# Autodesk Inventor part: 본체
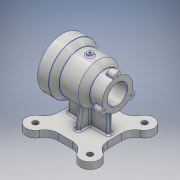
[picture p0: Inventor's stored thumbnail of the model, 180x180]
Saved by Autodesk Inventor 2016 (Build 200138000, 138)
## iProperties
Created: 2017-03
Part Number: 본체
Material: 알루미늄 6061
Document SubType Name: Modeling
Designer: USER
Density: 2.7 g/cm^3
Appearance: 알루미늄 - 평지
Mass: 1015.99 g
Surface Area: 852.536 cm^2
Volume: 376.292 cm^3
Author: USER
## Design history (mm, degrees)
sketch "스케치1"
  geometry: L1 (0, 0)-(-100, 0); L2 (0, 35)-(0, 45); L3 (0, 45)-(-20, 45); L4 (-20, 45)-(-31, 36.63); L5 (-31, 36.63)-(-65, 36.63); L6 (-65, 36.63)-(-77, 27.5); L7 (-77, 27.5)-(-100, 27.5); L8 (0, 35)-(-20, 35); L9 (-23, 32)-(-23, 29); L10 (-26, 26)-(-67, 26); L11 (-70, 23)-(-70, 20.5); L12 (-73, 17.5)-(-100, 17.5); L13 (-100, 17.5)-(-100, 27.5); A1 r 3 centre (-20, 32) between (-20, 35) and (-23, 32); A2 r 3 centre (-67, 23) between (-67, 26) and (-70, 23); A3 r 3 centre (-26, 29) between (-26, 26) and (-23, 29); A4 r 3 centre (-73, 20.5) between (-73, 17.5) and (-70, 20.5); 5 further points
  constraints: 26 end point, 8 point on circle, 8 point on line, 8 tangent, 6 perpendicular, 4 centre point, 3 parallel, 2 equal radius, 1 horizontal, 1 midpoint, 1 vertical, 1 vertical alignment
  dimensions: "d0" = 100 distance between parallel lines of L13 L2; "d1" = 90 diameter of L3 L1; "d2" = 70 diameter of L8 L1; "d3" = 52 diameter of L10 L1; "d4" = 23 distance between parallel lines of L9 L2; "d5" = 47 distance between parallel lines of L11 L9; "d6" = 35 diameter of L12 L1; "d7" = 20 distance of L2.end L3.end; "d8" = 31 horizontal distance of L4.end L2.end; "d9" = 65 horizontal distance of L2.end L5.end; "d10" = 23 distance of L6.end L7.end; "d11" = 55 diameter of L7 L1; "d20" = 3 radius of A1; "d24" = 3 radius of A4
revolve "회전1" sketch "스케치1" stored, may be unused: angle "d12" = 90 deg
sketch "스케치2"
  geometry: L1 (0, 0)-(13.75, 23.816); L2 (0, 0)-(-27.5, 0); L3 (0, 0)-(13.75, -23.816); A1 r 7 centre (-27.5, 0) between (-26.609, 6.943) and (-26.609, -6.943); A2 r 7 centre (13.75, -23.816) between (7.292, -26.516) and (19.317, -19.573); A3 r 7 centre (13.75, 23.816) between (19.317, 19.573) and (7.292, 26.516); 2 further points
  constraints: 6 end point, 6 point on circle, 3 centre point, 1 horizontal, 1 horizontal alignment, 10 other
  dimensions: "d13" = 120 deg angle of L1 L2; "d14" = 120 deg angle of L2 L3; "d15" = 14 diameter of A1; "d16" = 14 diameter of A3; "d17" = 14 diameter of A2
extrude "돌출1" join sketch "스케치2" distance "d18" = 15; taper "d19" = 0 deg
fillet "모깎기1" dims "d21" = 3
fillet "모깎기2" dims "d22" = 1
fillet "모깎기3" dims "d23" = 1
node "작업 평면1"
sketch "스케치8"
  geometry: L1 (50, 0)-(99.497, 49.497); L2 (50, 0)-(120, 0); L3 (5, 45)-(95, 45); L4 (95, 45)-(95, -45); L5 (95, -45)-(5, -45); L6 (5, -45)-(5, 45); L7 (5, 0)-(95, 0); L8 (50, -45)-(50, 45); A1 r 70 centre (50, 0) between (99.497, 49.497) and (120, 0); 1 further point
  constraints: 16 end point, 5 midpoint, 2 horizontal, 2 horizontal alignment, 2 parallel, 2 point on circle, 1 centre point, 1 perpendicular
  dimensions: "d82" = 140 diameter of A1; "d83" = 50 distance of L1.start point (0, 0); "d84" = 45 deg angle of L2 L1; "d88" = 90 distance of L3.start L3.end; "d89" = 90 distance of L5.end L3.start
extrude "돌출3" join sketch "스케치8" distance "d90" = 12; taper "d91" = 0 deg
sketch "스케치9"
  geometry: L1 (5, -45)-(5, 45) reference; L2 (5, 0)-(95, 0); L3 (95, 45)-(95, -45) reference; L4 (95, -45)-(5, -45) reference; L5 (5, 45)-(95, 45) reference; L6 (50, 45)-(50, -45); L7 (50, 0)-(99.497, 49.497); A1 r 70 centre (50, 0) between (99.497, 49.497) and (110.143, 35.816); A2 r 17 centre (99.497, 49.497) between (107.796, 34.661) and (84.661, 57.796); A3 r 25 centre (120, 12.842) between (110.143, 35.816) and (95, 12.842); A4 r 25 centre (62.842, 70) between (62.842, 45) and (85.816, 60.143); 1 further point
  constraints: 11 point on circle, 6 end point, 5 midpoint, 4 centre point, 4 tangent, 2 point on line, 1 coincident
  dimensions: "d92" = 140 diameter of A1; "d93" = 45 deg angle of L2 L7; "d94" = 34 diameter of A2; "d97" = 50 diameter of A3; "d98" = 50 diameter of A4
extrude "돌출4" join sketch "스케치9" distance "d99" = 12; taper "d100" = 0 deg
sketch "스케치11"
  geometry: C1 r 5 at (50, 0); 1 further point
  constraints: 1 centre point, 1 horizontal alignment
  dimensions: "d112" = 10 diameter of C1; "d113" = 50 distance of C1.centre point (0, 0)
extrude "돌출5" cut sketch "스케치11" distance "d114" = 12; taper "d115" = 0 deg
sketch "스케치12"
  geometry: C1 r 5 at (50, 0); C2 r 5 at (50, 0) reference; 1 further point
  constraints: 1 centre point, 1 concentric
  dimensions: "d119" = 10 diameter of C1
extrude "돌출6" join sketch "스케치12" distance "d120" = 12; taper "d121" = 0 deg
sketch "스케치13"
  geometry: L1 (16.497, -70)-(16.497, -82) reference; L2 (-116.497, -70)-(-116.497, -82) reference; L3 (-13, -45)-(-13, -70); L4 (-87, -27.5)-(-87, -70); L5 (-84.661, -70)-(-62.842, -70) reference; L6 (-76.732, -27.704)-(-65, -36.63) reference; L7 (-37.158, -82)-(-62.842, -82) reference; L8 (-50, 46.891)-(-50, -110.432); L9 (-19.663, -45)-(0, -45) reference; L10 (-100, -19.881)-(-88, -19.881) reference; L11 (-100, -19.881)-(-100, -19.881) reference; L12 (-88, -19.881)-(-100, -19.881) reference; L13 (-84, -10.332)-(-84, -16.905) reference; L14 (-100, -6.513)-(-88, -6.513) reference; L15 (-100, -6.513)-(-100, 26.395) reference; L16 (-88, 26.395)-(-100, 26.395) reference; L17 (-84, 27.237)-(-84, 27.237) reference; L18 (-100, 26.395)-(-88, 26.395) reference; L19 (-100, 26.395)-(-100, -6.513) reference; L20 (-88, -6.513)-(-100, -6.513) reference; L21 (-84, -16.905)-(-84, -10.332) reference; L22 (-77.337, -27.5)-(-77.337, 27.5) reference; L23 (-100, -27.5)-(-77.337, -27.5) reference; L24 (-13, -70)-(-87, -70); L25 (16.497, -70)-(-15.339, -70) reference; L26 (-20.268, -44.796)-(-20.268, 44.796) reference; L27 (-13, -45)-(-20.268, -44.796); L28 (-30.732, 36.835)-(-30.732, -36.835) reference; L29 (-20.268, -44.796)-(-30.732, -36.835); L30 (-30.732, -36.835)-(-20.268, -44.796) reference; L31 (-30.732, -36.835)-(-77.337, -27.5); 2 further points
  constraints: 14 end point, 3 point on line, 3 vertical, 2 collinear, 6 other
  dimensions: "d122" = 50 distance from line of point (0, 0) L8; "d123" = 37 distance between parallel lines of L3 L8; "d124" = 37 distance between parallel lines of L4 L8
extrude "돌출7" join sketch "스케치13" stored distance "d125" = 8; taper "d126" = 0 deg
node "작업 평면2"
sketch "스케치14"
  geometry: L1 (-25, -70)-(-19.784, -40.418); L2 (25, -70)-(19.784, -40.418); L3 (0, 0)-(0, -82); L4 (-12.842, -82)-(12.842, -82) reference; L5 (-34.661, -70)-(-66.497, -70) reference; L6 (-34.661, -70)-(-12.842, -70) reference; L7 (12.842, -70)-(34.661, -70) reference; A1 r 45 centre (0, 0) between (-19.784, -40.418) and (19.784, -40.418) reference; 2 further points
  constraints: 6 end point, 2 point on circle, 2 point on line, 1 midpoint
  dimensions: "d129" = 100 deg angle of L5 L1; "d130" = 25 distance from line of L3 L1.start; "d131" = 100 deg angle of L7 L2; "d132" = 25 distance from line of L2.start L3
feature "리브1" dims "d133" = 1, "d134" = 8, "d135" = 0, "d136" = 0, "d137" = 1, "d138" = 1
feature "리브2" dims "d139" = 1, "d140" = 8, "d141" = 0, "d142" = 0, "d143" = 1, "d144" = 1
fillet "모깎기4" dims "d145" = 3
sketch "스케치15" dims "d146" = 80
  geometry: 8 further points
  constraints: 2 horizontal alignment, 1 coincident, 9 other
  dimensions: "d149" = 360 deg dimension on point (0, 0) point (40, 0) (derived)
hole "구멍1" sketch "스케치15" at (40, 0), (20, 34.641), (-20, 34.641), (-40, 0), (-20, -34.641), (20, -34.641) diameter "d151" = 3.242; stored, may be unused: countersink angle "d155" = 90 deg, drill point angle "d157" = 118 deg; dims "d152" = 9, "d153" = 4, "d154" = 2, "d156" = 11
sketch "스케치16"
  geometry: C1 r 5 at (99.497, 49.497); C2 r 5 at (99.497, -49.497); C3 r 5 at (0.503, -49.497); C4 r 5 at (0.503, 49.497); A1 r 17 centre (99.497, 49.497) between (107.796, 34.661) and (84.661, 57.796) reference; A2 r 17 centre (99.497, -49.497) between (84.661, -57.796) and (107.796, -34.661) reference; A3 r 17 centre (0.503, -49.497) between (-7.796, -34.661) and (15.339, -57.796) reference; A4 r 17 centre (0.503, 49.497) between (15.339, 57.796) and (-7.796, 34.661) reference; 1 further point
  constraints: 4 centre point, 4 concentric
  dimensions: "d158" = 10 diameter of C1; "d159" = 10 diameter of C2; "d160" = 10 diameter of C4; "d161" = 10 diameter of C3
extrude "돌출8" cut sketch "스케치16" stored distance "d162" = 8; taper "d163" = 0 deg
sketch "스케치17"
  geometry: 4 further points
  constraints: 1 horizontal alignment, 4 other
  dimensions: "d164" = 27.5 distance of point (27.5, 0) point (0, 0); "d167" = 360 deg dimension on point (27.5, 0) point (0, 0) (derived)
hole "구멍2" sketch "스케치17" at (0, 0), (41.25, -23.816), (41.25, 23.816) diameter "d169" = 3.242; stored, may be unused: countersink angle "d173" = 90 deg, drill point angle "d175" = 118 deg; dims "d170" = 9, "d171" = 4, "d172" = 2, "d174" = 11
node "작업 평면3"
sketch "스케치18"
  geometry: C1 r 5 at (50, 0); 1 further point
  constraints: 1 centre point, 1 horizontal alignment
  dimensions: "d177" = 10 diameter of C1; "d178" = 50 distance of C1.centre point (0, 0)
extrude "돌출9" join sketch "스케치18" distance "d179" = 14; taper "d180" = 0 deg
fillet "모깎기5" dims "d181" = 3
sketch "스케치19"
  geometry: C1 r 5 at (0, 0) reference; 2 further points
  constraints: 1 coincident
hole "구멍3" sketch "스케치19" at (0, 0) diameter "d182" = 4.134; stored, may be unused: countersink angle "d186" = 90 deg, drill point angle "d188" = 118 deg; dims "d183" = 10, "d184" = 4, "d185" = 2, "d187" = 14.2
node "솔리드1"
pattern_circular "원형 패턴1" dims angle "d117" = 360 deg
node "투영된 루프1"
other parameters: "d25" = -82, "d79" = 34, "d176" = 26
